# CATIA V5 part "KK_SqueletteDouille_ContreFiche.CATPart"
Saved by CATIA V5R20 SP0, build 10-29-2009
Part number: Squelette_douille_contre_fiche
Bounding box of the stored display mesh (mm): x -2696 to -1945.905, y 859.662 to 1252.338, z -320 to 600
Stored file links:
  G:\Khaled_CFAO_2011\ST2M\ST2M_GR2\aboulegue\Khaled\CAD_thinkMOTION\KK_SqueletteDouille_ContreFiche.CATPart
  G:\Khaled_CFAO_2011\ST2M\ST2M_GR2\aboulegue\Khaled\CAD_thinkMOTION\KK_Train_Atterrissage.CATProduct
  G:\Khaled_CFAO_2011\ST2M\ST2M_GR2\aboulegue\Khaled\CAD_thinkMOTION\KK_SqueletteBati_Avion.CATPart
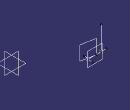
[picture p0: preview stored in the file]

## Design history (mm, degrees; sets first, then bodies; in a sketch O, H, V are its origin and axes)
Set1
  Point1 "Point.18": linked copy from another document
  Point2 "Point.12": linked copy from another document
  Plane1 "Plan reference contre fiche superieue": linked copy from another document
  Plane2 "Plan reference": linked copy from another document
  Line1: linked copy from another document
Set2 "Set squelette douille contre fiche"
  Line2: type PtPt, FirstPoint Point1, SecondPoint Point2
  Line3: type Normal, RefPoint Point2, RefSkin Plane1, Start -200, End 200
  Line4: type Normal, RefPoint Point1, RefSkin Plane2, Start -200, End 200
  Plane3 "Plan douille contre fiche": type 2Lines, Element1 Line2, Element2 Line1
Body1 (main body)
